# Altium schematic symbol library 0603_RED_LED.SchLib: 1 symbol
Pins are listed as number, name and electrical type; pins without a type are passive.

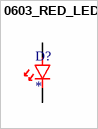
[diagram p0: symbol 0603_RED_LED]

## 0603_RED_LED
designator D?
footprint 0603_LED
pins: 1 A, 2 C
